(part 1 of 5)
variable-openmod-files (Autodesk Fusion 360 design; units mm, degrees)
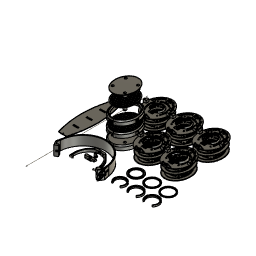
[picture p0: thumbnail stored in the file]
sketch "Pad Mount Start" plane through (0, 0, 0) normal (0, 0, 1) x axis (1, 0, 0)
  curve K1 (0, 53) -> (0, -53)
  curve K2 (-43, 0) -> (43, 0)
  curve K3 (0, 41) -> (0, -41)
  curve K4 (-31, 0) -> (31, 0)
  curve K5 (0, 43) -> (0, -43)
  curve K6 (-33, 0) -> (33, 0)
  line L1 (29.0688, 20.3542) -> (0, 0)
  line L2 (35.4865, 0) -> (0, 0)
  line L3 (20.8361, 33.3448) -> (0, 0)
  line L4 (39.3194, 0) -> (0, 0)
  curve K7 (0, -35.5) -> (0, 35.5)
  curve K8 (25.5, 0) -> (-25.5, 0)
  line L5 (29.0688, -20.3542) -> (0, 0)
  line L6 (20.8361, -33.3448) -> (0, 0)
  line L7 (0, 20) -> (0, 2.5)
  line L8 (-29.0688, -20.3542) -> (0, 0)
  line L9 (-20.8361, -33.3448) -> (0, 0)
  line L10 (-29.0688, 20.3542) -> (0, 0)
  line L11 (-20.8361, 33.3448) -> (0, 0)
  line L12 (37.023, 0) -> (0, 0)
  line L13 (11.725, -5.6147) -> (15.1969, -7.6193)
  line L14 (15.1969, 7.6193) -> (11.725, 5.6147)
  line L15 (1, 10.9545) -> (1, 6.9282)
  line L16 (6.5, -2.5981) -> (9.9868, -4.6112)
  line L17 (10.725, 7.3468) -> (14.1969, 9.3513)
  line L18 (1, 16.9706) -> (1, 12.9615)
  line L19 (11.43, 15.1775) -> (14.6475, 19.0119)
  line L20 (1, 23.9792) -> (1, 18.9737)
  line L21 (-1, 18.9737) -> (-1, 23.9792)
  line L22 (-14.6475, 19.0119) -> (-11.43, 15.1775)
  line L23 (-12.9621, 13.8919) -> (-16.1795, 17.7263)
  line L24 (-23.4412, 5.1487) -> (-18.5118, 4.2796)
  line L25 (-18.8591, 2.3099) -> (-23.7885, 3.1791)
  line L26 (-21.2666, -11.1236) -> (-16.9317, -8.6208)
  line L27 (-15.9317, -10.3529) -> (-20.2666, -12.8556)
  line L28 (-9.141, -22.191) -> (-7.4291, -17.4874)
  line L29 (-5.5497, -18.1714) -> (-7.2617, -22.8751)
  line L30 (7.2617, -22.8751) -> (5.5497, -18.1714)
  line L31 (7.4291, -17.4874) -> (9.141, -22.191)
  line L32 (20.2666, -12.8556) -> (15.9317, -10.3529)
  line L33 (16.9317, -8.6208) -> (21.2666, -11.1236)
  line L34 (23.7885, 3.1791) -> (18.8591, 2.3099)
  line L35 (18.5118, 4.2796) -> (23.4412, 5.1487)
  line L36 (16.1795, 17.7263) -> (12.9621, 13.8919)
  line L37 (-14.1969, 9.3513) -> (-10.725, 7.3468)
  line L38 (-1, 12.9615) -> (-1, 16.9706)
  line L39 (-11.725, 5.6147) -> (-15.1969, 7.6193)
  line L40 (-15.1969, -7.6193) -> (-11.725, -5.6147)
  line L41 (-9.9868, -4.6112) -> (-6.5, -2.5981)
  line L42 (-1, 6.9282) -> (-1, 10.9545)
  line L43 (8.9868, -6.3433) -> (5.5, -4.3301)
  line L44 (-5.5, -4.3301) -> (-8.9868, -6.3433)
  line L45 (-10.725, -7.3468) -> (-14.1969, -9.3513)
  line L46 (-1, -16.9706) -> (-1, -12.9615)
  line L47 (14.1969, -9.3513) -> (10.725, -7.3468)
  line L48 (1, -12.9615) -> (1, -16.9706)
  closed curve K9 centre (0, 0)
  closed curve K10 centre (0, 0)
  closed curve K11 centre (0, 0)
  circle C1 centre (0, 0) radius 24
  circle C2 centre (0, 0) radius 25.5
  circle C3 centre (0, 0) radius 29.5
  closed curve K12 centre (0, 0)
  arc A1 centre (0, 0) radius 17 clockwise from (15.1969, 7.6193) to (15.1969, -7.6193)
  arc A2 centre (0, 0) radius 13 clockwise from (11.725, 5.6147) to (11.725, -5.6147)
  arc A3 centre (0, 0) radius 7 clockwise from (1, 6.9282) to (6.5, -2.5981)
  arc A4 centre (0, 0) radius 11 clockwise from (1, 10.9545) to (9.9868, -4.6112)
  arc A5 centre (0, 0) radius 17 clockwise from (1, 16.9706) to (14.1969, 9.3513)
  arc A6 centre (0, 0) radius 13 clockwise from (1, 12.9615) to (10.725, 7.3468)
  arc A7 centre (0, 0) radius 24 clockwise from (14.6475, 19.0119) to (16.1795, 17.7263)
  arc A8 centre (0, 0) radius 19 clockwise from (1, 18.9737) to (11.43, 15.1775)
  arc A9 centre (0, 0) radius 24 clockwise from (-1, 23.9792) to (1, 23.9792)
  arc A10 centre (0, 0) radius 19 clockwise from (-11.43, 15.1775) to (-1, 18.9737)
  arc A11 centre (0, 0) radius 24 clockwise from (-16.1795, 17.7263) to (-14.6475, 19.0119)
  arc A12 centre (0, 0) radius 19 clockwise from (-18.5118, 4.2796) to (-12.9621, 13.8919)
  arc A13 centre (0, 0) radius 24 clockwise from (-23.7885, 3.1791) to (-23.4412, 5.1487)
  arc A14 centre (0, 0) radius 19 clockwise from (-16.9317, -8.6208) to (-18.8591, 2.3099)
  arc A15 centre (0, 0) radius 24 clockwise from (-20.2666, -12.8556) to (-21.2666, -11.1236)
  arc A16 centre (0, 0) radius 19 clockwise from (-7.4291, -17.4874) to (-15.9317, -10.3529)
  arc A17 centre (0, 0) radius 24 clockwise from (-7.2617, -22.8751) to (-9.141, -22.191)
  arc A18 centre (0, 0) radius 19 clockwise from (5.5497, -18.1714) to (-5.5497, -18.1714)
  arc A19 centre (0, 0) radius 24 clockwise from (9.141, -22.191) to (7.2617, -22.8751)
  arc A20 centre (0, 0) radius 19 clockwise from (15.9317, -10.3529) to (7.4291, -17.4874)
  arc A21 centre (0, 0) radius 24 clockwise from (21.2666, -11.1236) to (20.2666, -12.8556)
  arc A22 centre (0, 0) radius 19 clockwise from (18.8591, 2.3099) to (16.9317, -8.6208)
  arc A23 centre (0, 0) radius 24 clockwise from (23.4412, 5.1487) to (23.7885, 3.1791)
  arc A24 centre (0, 0) radius 19 clockwise from (12.9621, 13.8919) to (18.5118, 4.2796)
  arc A25 centre (0, 0) radius 13 clockwise from (-10.725, 7.3468) to (-1, 12.9615)
  arc A26 centre (0, 0) radius 17 clockwise from (-14.1969, 9.3513) to (-1, 16.9706)
  arc A27 centre (0, 0) radius 17 clockwise from (-15.1969, -7.6193) to (-15.1969, 7.6193)
  arc A28 centre (0, 0) radius 13 clockwise from (-11.725, -5.6147) to (-11.725, 5.6147)
  arc A29 centre (0, 0) radius 7 clockwise from (-6.5, -2.5981) to (-1, 6.9282)
  arc A30 centre (0, 0) radius 11 clockwise from (-9.9868, -4.6112) to (-1, 10.9545)
  arc A31 centre (0, 0) radius 7 clockwise from (5.5, -4.3301) to (-5.5, -4.3301)
  arc A32 centre (0, 0) radius 11 clockwise from (8.9868, -6.3433) to (-8.9868, -6.3433)
  arc A33 centre (0, 0) radius 17 clockwise from (-1, -16.9706) to (-14.1969, -9.3513)
  arc A34 centre (0, 0) radius 13 clockwise from (-1, -12.9615) to (-10.725, -7.3468)
  arc A35 centre (0, 0) radius 13 clockwise from (10.725, -7.3468) to (1, -12.9615)
  arc A36 centre (0, 0) radius 17 clockwise from (14.1969, -9.3513) to (1, -16.9706)
  circle C4 centre (0, 0) radius 5
  point P3 (0, -53)
  point P4 (0, 53)
  point P5 (43, 0)
  point P6 (-43, 0)
  point P1 (0, 0)
  point P2 (0, 0)
  point P8 (0, -41)
  point P9 (0, 41)
  point P10 (31, 0)
  point P11 (-31, 0)
  point P7 (0, 0)
  point P13 (0, -43)
  point P14 (0, 43)
  point P15 (33, 0)
  point P16 (-33, 0)
  point P17 (0, 0)
  point P20 (0, 0)
  point P21 (29.0688, 20.3542)
  point P23 (0, 0)
  point P24 (20.8361, 33.3448)
  point P27 (0, 35.5)
  point P28 (0, -35.5)
  point P29 (-25.5, 0)
  point P30 (25.5, 0)
  point P31 (0, 0)
  point P32 (29.0688, -20.3542)
  point P33 (0, 0)
  point P34 (20.8361, -33.3448)
  point P41 (0, 0)
  point P42 (-29.0688, 20.3542)
  point P43 (0, 0)
  point P44 (-20.8361, 33.3448)
  point P37 (0, 0)
  point P38 (-29.0688, -20.3542)
  point P39 (0, 0)
  point P40 (-20.8361, -33.3448)
  coincident K9 P3
  coincident K9 P4
  coincident K9 P5
  coincident K9 P6
  coincident P1 P2
  vertical K1
  coincident K10 P8
  coincident K10 P9
  coincident K10 P10
  coincident K10 P11
  coincident P1 P7
  perpendicular K2 K3
  coincident K11 P13
  coincident K11 P14
  coincident K11 P15
  coincident K11 P16
  concentric K9 K11
  perpendicular K4 K5
  concentric K11 C1
  concentric K9 C2
  concentric K9 C3
  horizontal L2
  coincident P17 P20
  coincident K11 P21
  horizontal L4
  coincident P7 P23
  coincident K11 P24
  coincident K12 P27
  coincident K12 P28
  coincident K12 P29
  coincident K12 P30
  concentric K10 K12
  parallel K3 K7
  symmetric P20 L2 P31
  symmetric P21 L2 P32
  symmetric L2 P23 P33
  symmetric L2 P24 P34
  symmetric P20 L7 P41
  symmetric P21 L7 P42
  symmetric P23 L7 P43
  symmetric P24 L7 P44
  symmetric P31 L7 P37
  symmetric P32 L7 P38
  symmetric P33 L7 P39
  symmetric P34 L7 P40
  horizontal L12
  dimension "d1" distance K9 = 106
  dimension "d2" = 86
  dimension "d3" distance K10 = 82
  dimension "d4" = 62
  dimension "d5" distance K11 = 86
  dimension "d6" = 66
  dimension "d7" diameter C1 = 48
  dimension "d8" diameter C2 = 51
  dimension "d9" diameter C3 = 59
  dimension "d10" angle L1 L2 = 35
  dimension "d11" angle L3 L4 = 58
  dimension "d12" distance K12 = 71
  dimension "d13" = 51
  dimension "d660" angle P16 = 20
extrude "Extrude1" new body sketch "Pad Mount Start" profile of K9 K11 along normal blind 2
extrude "Extrude2" add sketch "Pad Mount Start" profile of K10 K11 C2 C3 along normal blind 5
extrude "Extrude3" add sketch "Pad Mount Start" profile of C1 C2 A7 A9 A11 A13 A15 A17 A19 A21 A23 along normal blind 2.5
extrude "Extrude4" add sketch "Pad Mount Start" profile of C1 A1 L13 L14 A2 L15 A3 L16 A4 A5 L17 L18 A6 A7 L19 A8 L20 A9 L21 A10 L22 A11 L23 A12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 along normal blind 1.5
component_from_bodies "Body->Comp1"
sketch "Sketch2" plane through (0, 0, 5) normal (0, 0, 1) x axis (-1, 0, 0)
  line L1 (-20.8361, -33.3448) -> (0, 0)
  line L2 (-29.0688, -20.3542) -> (0, 0)
  line L3 (-29.0688, 20.3542) -> (0, 0)
  line L4 (-20.8361, 33.3448) -> (0, 0)
  line L5 (20.8361, 33.3448) -> (0, 0)
  line L6 (29.0688, 20.3542) -> (0, 0)
  line L7 (29.0688, -20.3542) -> (0, 0)
  line L8 (20.8361, -33.3448) -> (0, 0)
  curve K1 (0, 41) -> (0, -41)
  curve K2 (-31, 0) -> (31, 0)
  curve K3 (-27, 0) -> (27, 0)
  curve K4 (0, -37) -> (0, 37)
  circle C1 centre (0, 0) radius 25.5
  closed curve K5 centre (0, 0)
  closed curve K6 centre (0, 0)
  closed curve K7 centre (0, 0)
  circle C2 centre (0, 0) radius 29.5
  circle C3 centre (0, 0) radius 33.5
  point P20 (0, -41)
  point P21 (0, 41)
  point P22 (31, 0)
  point P23 (-31, 0)
  point P15 (0, 0)
  point P16 (0, 0)
  point P25 (27, 0)
  point P26 (-27, 0)
  point P27 (0, 37)
  point P28 (0, -37)
  point P4 (0, 0)
  point P24 (0, 0)
  point P9 (0, 0)
  point P29 (0, 0)
  coincident K6 P20
  coincident K6 P21
  coincident K6 P22
  coincident K6 P23
  coincident P15 P16
  coincident K7 P25
  coincident K7 P26
  coincident K7 P27
  coincident K7 P28
  coincident P4 P24
  parallel K2 K3
  coincident P9 P29
  concentric K6 C3
  dimension "d37" distance K6 = 82
  dimension "d38" = 62
  dimension "d41" distance K7 = 54
  dimension "d42" = 74
  dimension "d43" diameter C2 = 59
  dimension "d44" diameter C3 = 67
extrude "Extrude2" cut sketch "Sketch2" profile of L1 L2 L3 L4 L5 L6 L7 L8 K6 K7 C2 C3 against normal blind 5
sketch "Sketch3" plane through (0, 0, 0) normal (0, 0, -1) x axis (1, 0, 0)
  line L1 (17.7523, -28.4096) -> (15.6326, -25.0174)
  line L2 (-15.6326, -25.0174) -> (-17.7523, -28.4096)
  line L3 (-27.3973, -19.1838) -> (-24.0432, -16.8352)
  line L4 (-24.0432, 16.8352) -> (-27.3973, 19.1838)
  line L5 (-17.7523, 28.4096) -> (-15.6326, 25.0174)
  line L6 (15.6326, 25.0174) -> (17.7523, 28.4096)
  line L7 (27.3973, 19.1838) -> (24.0432, 16.8352)
  line L8 (24.0432, -16.8352) -> (27.3973, -19.1838)
  line L9 (12.9621, -13.8919) -> (16.1795, -17.7263)
  line L10 (23.4412, -5.1487) -> (18.5118, -4.2796)
  line L11 (18.8591, -2.3099) -> (23.7885, -3.1791)
  line L12 (21.2666, 11.1236) -> (16.9317, 8.6208)
  line L13 (15.9317, 10.3529) -> (20.2666, 12.8556)
  line L14 (9.141, 22.191) -> (7.4291, 17.4874)
  line L15 (5.5497, 18.1714) -> (7.2617, 22.8751)
  line L16 (-7.2617, 22.8751) -> (-5.5497, 18.1714)
  line L17 (-7.4291, 17.4874) -> (-9.141, 22.191)
  line L18 (-20.2666, 12.8556) -> (-15.9317, 10.3529)
  line L19 (-16.9317, 8.6208) -> (-21.2666, 11.1236)
  line L20 (-23.7885, -3.1791) -> (-18.8591, -2.3099)
  line L21 (-18.5118, -4.2796) -> (-23.4412, -5.1487)
  line L22 (-16.1795, -17.7263) -> (-12.9621, -13.8919)
  line L23 (-11.43, -15.1775) -> (-14.6475, -19.0119)
  line L24 (-1, -23.9792) -> (-1, -18.9737)
  line L25 (-1, -10.9545) -> (-1, -6.9282)
  line L26 (-6.5, 2.5981) -> (-9.9868, 4.6112)
  line L27 (-1, 12.9615) -> (-1, 16.9706)
  line L28 (-14.1969, 9.3513) -> (-10.725, 7.3468)
  line L29 (1, -12.9615) -> (1, -16.9706)
  line L30 (14.1969, -9.3513) -> (10.725, -7.3468)
  line L31 (11.725, -5.6147) -> (15.1969, -7.6193)
  line L32 (15.1969, 7.6193) -> (11.725, 5.6147)
  line L33 (-11.725, 5.6147) -> (-15.1969, 7.6193)
  line L34 (-15.1969, -7.6193) -> (-11.725, -5.6147)
  line L35 (-1, -16.9706) -> (-1, -12.9615)
  line L36 (-10.725, -7.3468) -> (-14.1969, -9.3513)
  line L37 (-8.9868, 6.3433) -> (-5.5, 4.3301)
  line L38 (5.5, 4.3301) -> (8.9868, 6.3433)
  line L39 (1, 16.9706) -> (1, 12.9615)
  line L40 (10.725, 7.3468) -> (14.1969, 9.3513)
  line L41 (9.9868, 4.6112) -> (6.5, 2.5981)
  line L42 (1, -6.9282) -> (1, -10.9545)
  line L43 (1, -18.9737) -> (1, -23.9792)
  line L44 (14.6475, -19.0119) -> (11.43, -15.1775)
  line L45 (22.8469, -24.5003) -> (0, 0)
  line L46 (33.5, 0) -> (0, 0)
  line L47 (-22.8469, -24.5003) -> (0, 0)
  line L48 (-33.5, 0) -> (0, 0)
  line L49 (-22.8469, 24.5003) -> (0, 0)
  line L50 (22.8469, 24.5003) -> (0, 0)
  arc A1 centre (0, 0) radius 33.5 clockwise from (17.7523, -28.4096) to (-17.7523, -28.4096)
  arc A2 centre (0, 0) radius 29.5 clockwise from (15.6326, -25.0174) to (-15.6326, -25.0174)
  closed curve K1 centre (0, 0)
  closed curve K2 centre (0, 0)
  arc A3 centre (0, 0) radius 33.5 clockwise from (-17.7523, 28.4096) to (17.7523, 28.4096)
  arc A4 centre (0, 0) radius 29.5 clockwise from (-15.6326, 25.0174) to (15.6326, 25.0174)
  closed curve K3 centre (0, 0)
  closed curve K4 centre (0, 0)
  arc A5 centre (0, 0) radius 24 clockwise from (23.4412, -5.1487) to (16.1795, -17.7263)
  arc A6 centre (0, 0) radius 19 clockwise from (18.5118, -4.2796) to (12.9621, -13.8919)
  arc A7 centre (0, 0) radius 19 clockwise from (16.9317, 8.6208) to (18.8591, -2.3099)
  arc A8 centre (0, 0) radius 24 clockwise from (21.2666, 11.1236) to (23.7885, -3.1791)
  arc A9 centre (0, 0) radius 19 clockwise from (7.4291, 17.4874) to (15.9317, 10.3529)
  arc A10 centre (0, 0) radius 24 clockwise from (9.141, 22.191) to (20.2666, 12.8556)
  arc A11 centre (0, 0) radius 19 clockwise from (-5.5497, 18.1714) to (5.5497, 18.1714)
  arc A12 centre (0, 0) radius 24 clockwise from (-7.2617, 22.8751) to (7.2617, 22.8751)
  arc A13 centre (0, 0) radius 19 clockwise from (-15.9317, 10.3529) to (-7.4291, 17.4874)
  arc A14 centre (0, 0) radius 24 clockwise from (-20.2666, 12.8556) to (-9.141, 22.191)
  arc A15 centre (0, 0) radius 19 clockwise from (-18.8591, -2.3099) to (-16.9317, 8.6208)
  arc A16 centre (0, 0) radius 24 clockwise from (-23.7885, -3.1791) to (-21.2666, 11.1236)
  arc A17 centre (0, 0) radius 19 clockwise from (-12.9621, -13.8919) to (-18.5118, -4.2796)
  arc A18 centre (0, 0) radius 24 clockwise from (-16.1795, -17.7263) to (-23.4412, -5.1487)
  arc A19 centre (0, 0) radius 19 clockwise from (-1, -18.9737) to (-11.43, -15.1775)
  arc A20 centre (0, 0) radius 24 clockwise from (-1, -23.9792) to (-14.6475, -19.0119)
  arc A21 centre (0, 0) radius 11 clockwise from (-1, -10.9545) to (-9.9868, 4.6112)
  arc A22 centre (0, 0) radius 7 clockwise from (-1, -6.9282) to (-6.5, 2.5981)
  arc A23 centre (0, 0) radius 17 clockwise from (-14.1969, 9.3513) to (-1, 16.9706)
  arc A24 centre (0, 0) radius 13 clockwise from (-10.725, 7.3468) to (-1, 12.9615)
  arc A25 centre (0, 0) radius 17 clockwise from (14.1969, -9.3513) to (1, -16.9706)
  arc A26 centre (0, 0) radius 13 clockwise from (10.725, -7.3468) to (1, -12.9615)
  arc A27 centre (0, 0) radius 17 clockwise from (15.1969, 7.6193) to (15.1969, -7.6193)
  arc A28 centre (0, 0) radius 13 clockwise from (11.725, 5.6147) to (11.725, -5.6147)
  arc A29 centre (0, 0) radius 17 clockwise from (-15.1969, -7.6193) to (-15.1969, 7.6193)
  arc A30 centre (0, 0) radius 13 clockwise from (-11.725, -5.6147) to (-11.725, 5.6147)
  arc A31 centre (0, 0) radius 17 clockwise from (-1, -16.9706) to (-14.1969, -9.3513)
  arc A32 centre (0, 0) radius 13 clockwise from (-1, -12.9615) to (-10.725, -7.3468)
  arc A33 centre (0, 0) radius 11 clockwise from (-8.9868, 6.3433) to (8.9868, 6.3433)
  arc A34 centre (0, 0) radius 7 clockwise from (-5.5, 4.3301) to (5.5, 4.3301)
  circle C1 centre (0, 0) radius 5
  arc A35 centre (0, 0) radius 17 clockwise from (1, 16.9706) to (14.1969, 9.3513)
  arc A36 centre (0, 0) radius 13 clockwise from (1, 12.9615) to (10.725, 7.3468)
  arc A37 centre (0, 0) radius 11 clockwise from (9.9868, 4.6112) to (1, -10.9545)
  arc A38 centre (0, 0) radius 7 clockwise from (6.5, 2.5981) to (1, -6.9282)
  arc A39 centre (0, 0) radius 19 clockwise from (11.43, -15.1775) to (1, -18.9737)
  arc A40 centre (0, 0) radius 24 clockwise from (14.6475, -19.0119) to (1, -23.9792)
  closed curve K5 centre (0, 0)
  circle C2 centre (0, 0) radius 33.5
  circle C3 centre (-22.8469, -24.5003) radius 2.2
  circle C4 centre (-22.8469, -24.5003) radius 4
  circle C5 centre (-22.8469, -24.5003) radius 4.5
  circle C6 centre (22.8469, -24.5003) radius 2.2
  circle C7 centre (22.8469, -24.5003) radius 4
  circle C8 centre (22.8469, -24.5003) radius 4.5
  circle C9 centre (-22.8469, 24.5003) radius 4.5
  circle C10 centre (-22.8469, 24.5003) radius 4
  circle C11 centre (-22.8469, 24.5003) radius 2.2
  circle C12 centre (22.8469, 24.5003) radius 4.5
  circle C13 centre (22.8469, 24.5003) radius 4
  circle C14 centre (22.8469, 24.5003) radius 2.2
  point P1 (0, 0)
  point P92 (0, 0)
  point P93 (22.8469, -24.5003)
  point P5 (0, 0)
  point P95 (0, 0)
  point P96 (-22.8469, -24.5003)
  point P100 (0, 0)
  point P101 (22.8469, 24.5003)
  point P98 (0, 0)
  point P99 (-22.8469, 24.5003)
  point P102 (-22.8469, -24.5003)
  point P103 (-22.8469, -24.5003)
  point P104 (-22.8469, -24.5003)
  point P105 (22.8469, -24.5003)
  concentric A1 C2
  horizontal L46
  coincident P1 P92
  coincident C2 P93
  horizontal L48
  coincident P5 P95
  coincident C2 P96
  symmetric P92 L46 P100
  symmetric P93 L46 P101
  symmetric L46 P95 P98
  symmetric L46 P96 P99
  coincident P96 P102
  coincident P96 P103
  coincident P96 P104
  coincident P93 P105
  concentric C6 C7
  concentric C6 C8
  symmetric L48 C3 C11
  symmetric L48 C4 C10
  symmetric L48 C5 C9
  symmetric L48 C6 C14
  symmetric L48 C7 C13
  symmetric L48 C8 C12
  dimension "d59" diameter C2 = 67
  dimension "d60" angle L45 L46 = 47
  dimension "d61" angle L47 L48 = 47
  dimension "d62" diameter C3 = 4.4
  dimension "d63" diameter C4 = 8
  dimension "d64" diameter C5 = 9
  dimension "d65" diameter C6 = 4.4
  dimension "d66" diameter C7 = 8
  dimension "d67" diameter C8 = 9
extrude "Extrude5" cut sketch "Sketch3" profile of C3 C6 C11 C14 against normal blind 5
extrude "Extrude6" cut sketch "Sketch3" profile of C3 C4 C6 C7 C10 C11 C13 C14 against normal blind 3
sketch "Sketch4" plane through (0, 0, 5) normal (0, 0, 1) x axis (-1, 0, 0)
  line L1 (-15.6326, -25.0174) -> (-17.7523, -28.4096)
  line L2 (17.7523, -28.4096) -> (15.6326, -25.0174)
  line L3 (24.0432, -16.8352) -> (27.3973, -19.1838)
  line L4 (27.3973, 19.1838) -> (24.0432, 16.8352)
  line L5 (15.6326, 25.0174) -> (17.7523, 28.4096)
  line L6 (-17.7523, 28.4096) -> (-15.6326, 25.0174)
  line L7 (-24.0432, 16.8352) -> (-27.3973, 19.1838)
  line L8 (-27.3973, -19.1838) -> (-24.0432, -16.8352)
  circle C1 centre (22.8469, -24.5003) radius 2.2
  circle C2 centre (22.8469, 24.5003) radius 2.2
  circle C3 centre (-22.8469, -24.5003) radius 2.2
  circle C4 centre (-22.8469, 24.5003) radius 2.2
  arc A1 centre (0, 0) radius 29.5 clockwise from (15.6326, -25.0174) to (-15.6326, -25.0174)
  arc A2 centre (0, 0) radius 33.5 clockwise from (17.7523, -28.4096) to (-17.7523, -28.4096)
  closed curve K1 centre (0, 0)
  closed curve K2 centre (0, 0)
  arc A3 centre (0, 0) radius 29.5 clockwise from (-15.6326, 25.0174) to (15.6326, 25.0174)
  arc A4 centre (0, 0) radius 33.5 clockwise from (-17.7523, 28.4096) to (17.7523, 28.4096)
  closed curve K3 centre (0, 0)
  closed curve K4 centre (0, 0)
  circle C5 centre (0, 0) radius 25.5
  closed curve K5 centre (0, 0)
  circle C6 centre (22.8469, -24.5003) radius 4.5
  circle C7 centre (-22.8469, -24.5003) radius 4.5
  circle C8 centre (22.8469, 24.5003) radius 4.5
  circle C9 centre (-22.8469, 24.5003) radius 4.5
  concentric C1 C6
  concentric C3 C7
  concentric C2 C8
  concentric C4 C9
  dimension "d72" diameter C6 = 9
  dimension "d73" diameter C7 = 9
  dimension "d74" diameter C8 = 9
  dimension "d75" diameter C9 = 9
extrude "Extrude7" add sketch "Sketch4" profile of K5 C6 C7 C8 C9 against normal blind 3
extrude "Extrude8" cut of existing geometry blind -1
work_plane "WorkPlane1" AlongDistance 20
sketch "Driver Clamp" plane through (0, 0, 20) normal (0, 0, 1) x axis (1, 0, 0)
  curve K1 (0, 55) -> (0, -55)
  curve K2 (-45, 0) -> (45, 0)
  line L1 (29.0688, -20.3542) -> (0, 0)
  line L2 (20.8361, -33.3448) -> (0, 0)
  line L3 (-20.8361, -33.3448) -> (0, 0)
  line L4 (-29.0688, -20.3542) -> (0, 0)
  line L5 (-29.0688, 20.3542) -> (0, 0)
  line L6 (-20.8361, 33.3448) -> (0, 0)
  curve K3 (0, 41) -> (0, -41)
  curve K4 (-31, 0) -> (31, 0)
  curve K5 (-27, 0) -> (27, 0)
  curve K6 (0, -37) -> (0, 37)
  line L7 (20.8361, 33.3448) -> (0, 0)
  line L8 (29.0688, 20.3542) -> (0, 0)
  closed curve K7 centre (0, 0)
  circle C1 centre (22.8469, -24.5003) radius 2.2
  circle C2 centre (-22.8469, -24.5003) radius 2.2
  circle C3 centre (-22.8469, 24.5003) radius 2.2
  circle C4 centre (22.8469, 24.5003) radius 2.2
  circle C5 centre (0, 0) radius 25.2
  circle C6 centre (0, 0) radius 27.5
  circle C7 centre (0, 0) radius 29.5
  circle C8 centre (0, 0) radius 33.5
  closed curve K8 centre (0, 0)
  closed curve K9 centre (0, 0)
  point P3 (0, -55)
  point P4 (0, 55)
  point P5 (45, 0)
  point P6 (-45, 0)
  point P1 (0, 0)
  point P2 (0, 0)
  point P11 (0, 0)
  point P12 (0, 0)
  point P29 (0, -41)
  point P30 (0, 41)
  point P31 (31, 0)
  point P32 (-31, 0)
  point P33 (27, 0)
  point P34 (-27, 0)
  point P35 (0, 37)
  point P36 (0, -37)
  point P13 (0, 0)
  point P15 (0, 0)
  point P25 (0, 0)
  point P28 (0, 0)
  coincident K7 P3
  coincident K7 P4
  coincident K7 P5
  coincident K7 P6
  coincident P1 P2
  vertical K1
  coincident P1 P11
  coincident P1 P12
  coincident K8 P29
  coincident K8 P30
  coincident K8 P31
  coincident K8 P32
  coincident K9 P33
  coincident K9 P34
  coincident K9 P35
  coincident K9 P36
  coincident P13 P15
  parallel K4 K5
  coincident P25 P28
  concentric C8 K8
  dimension "d81" distance K7 = 110
  dimension "d82" = 90
  dimension "d83" diameter C5 = 50.4
  dimension "d84" diameter C6 = 55
  dimension "d85" distance K8 = 82
  dimension "d86" = 62
  dimension "d87" distance K9 = 54
  dimension "d88" = 74
  dimension "d89" diameter C7 = 59
  dimension "d90" diameter C8 = 67
extrude "Extrude9" new body sketch "Driver Clamp" profile of K7 C1 C2 C3 C4 C5 C6 L1 L2 L3 L4 L5 L6 C7 C8 K8 K9 L7 L8 along normal blind 2
sketch "Sketch6" plane through (0, 0, 22) normal (0, 0, 1) x axis (-1, 0, 0)
  line L1 (-24.0432, 16.8352) -> (-27.3973, 19.1838)
  line L2 (-27.3973, -19.1838) -> (-24.0432, -16.8352)
  line L3 (-17.7523, 28.4096) -> (-15.6326, 25.0174)
  line L4 (15.6326, 25.0174) -> (17.7523, 28.4096)
  line L5 (-15.6326, -25.0174) -> (-17.7523, -28.4096)
  line L6 (17.7523, -28.4096) -> (15.6326, -25.0174)
  line L7 (27.3973, 19.1838) -> (24.0432, 16.8352)
  line L8 (24.0432, -16.8352) -> (27.3973, -19.1838)
  line L9 (8, 35.5) -> (-8, 35.5)
  line L10 (8, 23.5) -> (8, 35.5)
  line L11 (-8, 23.5) -> (8, 23.5)
  line L12 (-8, 35.5) -> (-8, 23.5)
  line L13 (8, 23.5) -> (-8, 35.5)
  line L14 (-8, 23.5) -> (8, 35.5)
  closed curve K1 centre (0, 0)
  arc A1 centre (0, 0) radius 27.5 clockwise from (-26.4189, -7.6348) to (-26.4189, 7.6348)
  closed curve K2 centre (0, 0)
  closed curve K3 centre (0, 0)
  arc A2 centre (0, 0) radius 29.5 clockwise from (-15.6326, 25.0174) to (15.6326, 25.0174)
  arc A3 centre (0, 0) radius 33.5 clockwise from (-17.7523, 28.4096) to (17.7523, 28.4096)
  circle C1 centre (-22.8469, -24.5003) radius 2.2
  circle C2 centre (-22.8469, 24.5003) radius 2.2
  circle C3 centre (22.8469, -24.5003) radius 2.2
  circle C4 centre (0, 0) radius 25.2
  circle C5 centre (22.8469, 24.5003) radius 2.2
  arc A4 centre (0, 0) radius 29.5 clockwise from (15.6326, -25.0174) to (-15.6326, -25.0174)
  arc A5 centre (0, 0) radius 33.5 clockwise from (17.7523, -28.4096) to (-17.7523, -28.4096)
  closed curve K4 centre (0, 0)
  closed curve K5 centre (0, 0)
  closed curve K6 centre (0, 0)
  arc A6 centre (0, 0) radius 27.5 clockwise from (26.4189, 7.6348) to (26.4189, -7.6348)
  closed curve K7 centre (0, 0)
  point P31 (0, 29.5)
  point P29 (8, 23.5)
  point P30 (-8, 23.5)
  point P28 (8, 35.5)
  horizontal L9
  perpendicular L9 L10
  parallel L9 L11
  parallel L10 L12
  coincident L13 P31
  coincident L14 P31
  midpoint A2 P31
  dimension "d93" distance P29 P30 = 16
  dimension "d94" distance P28 P29 = 12
extrude "Extrude10" cut sketch "Sketch6" profile of A2 C4 L10 L12 against normal blind 2
extrude "Extrude11" add sketch "Sketch6" profile of A2 L3 A3 L4 L10 L12 against normal blind 2
sketch "Sketch7" plane through (0, 0, 22) normal (0, 0, 1) x axis (-1, 0, 0)
  line L1 (27.3973, 19.1838) -> (24.0432, 16.8352)
  line L2 (24.0432, -16.8352) -> (27.3973, -19.1838)
  line L3 (-15.6326, -25.0174) -> (-17.7523, -28.4096)
  line L4 (17.7523, -28.4096) -> (15.6326, -25.0174)
  line L5 (-8, 32.5308) -> (-8, 23.8964)
  line L6 (8, 23.8964) -> (8, 32.5308)
  line L7 (-24.0432, 16.8352) -> (-27.3973, 19.1838)
  line L8 (-27.3973, -19.1838) -> (-24.0432, -16.8352)
  line L9 (25.2, 0) -> (0, 0)
  line L10 (-25.2, 0) -> (0, 0)
  line L11 (19.4454, 19.4454) -> (0, 0)
  line L12 (27.5, 0) -> (0, 0)
  line L13 (-19.4454, 19.4454) -> (0, 0)
  line L14 (-27.5, 0) -> (0, 0)
  closed curve K1 centre (0, 0)
  closed curve K2 centre (0, 0)
  closed curve K3 centre (0, 0)
  closed curve K4 centre (0, 0)
  arc A1 centre (0, 0) radius 27.5 clockwise from (26.4189, 7.6348) to (26.4189, -7.6348)
  arc A2 centre (0, 0) radius 29.5 clockwise from (15.6326, -25.0174) to (-15.6326, -25.0174)
  arc A3 centre (0, 0) radius 33.5 clockwise from (17.7523, -28.4096) to (-17.7523, -28.4096)
  circle C1 centre (22.8469, 24.5003) radius 2.2
  circle C2 centre (22.8469, -24.5003) radius 2.2
  circle C3 centre (-22.8469, 24.5003) radius 2.2
  circle C4 centre (-22.8469, -24.5003) radius 2.2
  arc A4 centre (0, 0) radius 33.5 clockwise from (-8, 32.5308) to (8, 32.5308)
  arc A5 centre (0, 0) radius 25.2 clockwise from (8, 23.8964) to (-8, 23.8964)
  closed curve K5 centre (0, 0)
  arc A6 centre (0, 0) radius 27.5 clockwise from (-26.4189, -7.6348) to (-26.4189, 7.6348)
  closed curve K6 centre (0, 0)
  closed curve K7 centre (0, 0)
  circle C5 centre (0, 0) radius 21
  circle C6 centre (0, 0) radius 25.2
  circle C7 centre (0, 0) radius 27.5
  point P1 (0, 0)
  point P27 (0, 0)
  point P20 (8, 23.8964)
  point P2 (0, 0)
  point P29 (0, 0)
  point P31 (0, 0)
  point P34 (0, 0)
  point P35 (19.4454, 19.4454)
  point P37 (-19.4454, 19.4454)
  coincident P1 P27
  concentric K1 C6
  coincident P20 C6
  horizontal L9
  coincident P2 P29
  horizontal L10
  coincident P2 P31
  concentric K1 C7
  horizontal L12
  coincident P2 P34
  coincident C7 P35
  horizontal L14
  coincident C7 P37
  dimension "d99" diameter C5 = 42
  dimension "d102" diameter C7 = 55
  dimension "d103" angle L11 L12 = 45
  dimension "d104" angle L13 L14 = 45
extrude "Extrude12" add sketch "Sketch7" profile of A1 A5 A6 C5 C6 C7 L11 L13 along normal blind 4
chamfer "Chamfer1" distance 4.2 Rotate Angle 40
chamfer "Chamfer2" distance 4 Rotate Angle 45
sketch "Sketch8" plane through (0, 0, 22) normal (0, 0, 1) x axis (-1, 0, 0)
  line L1 (-27.3973, -19.1838) -> (-24.0432, -16.8352)
  line L2 (-24.0432, 16.8352) -> (-27.3973, 19.1838)
  line L3 (-17.8191, 17.8191) -> (-19.4454, 19.4454)
  line L4 (-8, 32.5308) -> (-8, 23.8964)
  line L5 (8, 23.8964) -> (8, 32.5308)
  line L6 (19.4454, 19.4454) -> (17.8191, 17.8191)
  line L7 (27.3973, 19.1838) -> (24.0432, 16.8352)
  line L8 (24.0432, -16.8352) -> (27.3973, -19.1838)
  line L9 (-15.6326, -25.0174) -> (-17.7523, -28.4096)
  line L10 (17.7523, -28.4096) -> (15.6326, -25.0174)
  curve K1 (0, 52.8) -> (0, -52.8)
  curve K2 (-42.8, 0) -> (42.8, 0)
  curve K3 (0, 50.8) -> (0, -50.8)
  curve K4 (-40.8, 0) -> (40.8, 0)
  line L11 (-8, 32.5308) -> (8, 32.5308)
  line L12 (-8, 55.0308) -> (-8, 32.5308)
  line L13 (8, 55.0308) -> (-8, 55.0308)
  line L14 (8, 32.5308) -> (8, 55.0308)
  line L15 (-6, 53.0308) -> (-6, 32.5308)
  line L16 (6, 53.0308) -> (-6, 53.0308)
  line L17 (6, 32.5308) -> (6, 53.0308)
  line L18 (17.2573, 46.032) -> (8, 49.8139)
  line L19 (18.1032, 47.8443) -> (17.2573, 46.032)
  line L20 (-17.2573, 46.032) -> (-8, 49.8139)
  line L21 (-18.1032, 47.8443) -> (-17.2573, 46.032)
  line L22 (6, 55.0308) -> (6, 53.0308)
  line L23 (-6, 55.0308) -> (-6, 53.0308)
  line L24 (-8, 54.1239) -> (-6, 55.0308)
  line L25 (8, 54.1239) -> (6, 55.0308)
  arc A1 centre (0, 0) radius 27.5 clockwise from (26.4189, -7.6348) to (-26.4189, -7.6348)
  closed curve K5 centre (0, 0)
  closed curve K6 centre (0, 0)
  closed curve K7 centre (0, 0)
  arc A2 centre (0, 0) radius 27.5 clockwise from (-26.4189, 7.6348) to (-19.4454, 19.4454)
  arc A3 centre (0, 0) radius 25.2 clockwise from (-17.8191, 17.8191) to (-8, 23.8964)
  arc A4 centre (0, 0) radius 33.5 clockwise from (-8, 32.5308) to (8, 32.5308)
  arc A5 centre (0, 0) radius 25.2 clockwise from (8, 23.8964) to (17.8191, 17.8191)
  arc A6 centre (0, 0) radius 27.5 clockwise from (19.4454, 19.4454) to (26.4189, 7.6348)
  closed curve K8 centre (0, 0)
  closed curve K9 centre (0, 0)
  closed curve K10 centre (0, 0)
  closed curve K11 centre (0, 0)
  arc A7 centre (0, 0) radius 29.5 clockwise from (15.6326, -25.0174) to (-15.6326, -25.0174)
  arc A8 centre (0, 0) radius 33.5 clockwise from (17.7523, -28.4096) to (-17.7523, -28.4096)
  circle C1 centre (22.8469, 24.5003) radius 2.2
  circle C2 centre (22.8469, -24.5003) radius 2.2
  circle C3 centre (-22.8469, 24.5003) radius 2.2
  circle C4 centre (-22.8469, -24.5003) radius 2.2
  closed curve K12 centre (0, 0)
  closed curve K13 centre (0, 0)
  point P32 (0, -52.8)
  point P33 (0, 52.8)
  point P34 (42.8, 0)
  point P35 (-42.8, 0)
  point P1 (0, 0)
  point P31 (0, 0)
  point P37 (0, -50.8)
  point P38 (0, 50.8)
  point P39 (40.8, 0)
  point P40 (-40.8, 0)
  point P14 (8, 32.5308)
  point P41 (8, 32.5308)
  point P49 (8, 49.8139)
  point P50 (17.2573, 46.032)
  point P51 (18.1032, 47.8443)
  point P52 (-8, 49.8139)
  point P53 (-17.2573, 46.032)
  point P54 (-18.1032, 47.8443)
  point P55 (6, 55.0308)
  point P56 (-6, 55.0308)
  point P57 (-8, 54.1239)
  point P58 (8, 54.1239)
  point P42 (-8, 32.5308)
  point P44 (8, 55.0308)
  coincident K12 P32
  coincident K12 P33
  coincident K12 P34
  coincident K12 P35
  coincident P1 P31
  vertical K1
  coincident K13 P37
  coincident K13 P38
  coincident K13 P39
  coincident K13 P40
  concentric A1 K13
  perpendicular K2 K3
  horizontal L11
  vertical L12
  horizontal L13
  vertical L14
  coincident P14 P41
  coincident L14 P49
  coincident K13 P49
  coincident K13 P50
  coincident K12 P51
  coincident K13 P52
  coincident L12 P52
  coincident K13 P53
  coincident K12 P54
  coincident L13 P55
  perpendicular L13 L22
  coincident L13 P56
  perpendicular L13 L23
  coincident L12 P57
  coincident K11 P57
  coincident L14 P58
  coincident K11 P58
  dimension "d111" distance K12 = 105.6
  dimension "d112" = 85.6
  dimension "d113" distance K13 = 101.6
  dimension "d114" = 81.6
  dimension "d115" distance P41 P42 = 16
  dimension "d116" distance P41 P44 = 22.5
  dimension "d117" = 2
  dimension "d118" distance P49 P50 = 10
  dimension "d119" distance P50 P51 = 2
  dimension "d120" distance P52 P53 = 10
  dimension "d121" distance P53 P54 = 2
extrude "Extrude13" add sketch "Sketch8" profile of K11 L13 L24 L25 against normal blind 2
extrude "Extrude14" add sketch "Sketch8" profile of K11 K12 K13 L12 L13 L14 L15 L17 L16 L19 L21 L24 L25 along normal blind 10.2
sketch "3.5mm Socket" plane through (0, -53.0308, 0) normal (0, 1, 0) x axis (-1, 0, 0)
  line L1 (6, 22) -> (-6, 22)
  line L2 (6, 32.2) -> (6, 22)
  line L3 (-6, 32.2) -> (6, 32.2)
  line L4 (-6, 22) -> (-6, 32.2)
  circle C1 centre (0, 27.1) radius 3.15
  dimension "d126" diameter C1 = 6.3
extrude "Extrude15" cut sketch "3.5mm Socket" profile of C1 against normal blind 2
chamfer "Chamfer3" distance 10.2 Rotate Angle 45
sketch "Sketch23" plane through (0, 0, 22) normal (0, 0, 1) x axis (-1, 0, 0)
  line L1 (-8, 54.1239) -> (-8, 51.8694)
  line L2 (8, 51.8694) -> (8, 54.1239)
  line L3 (17.2573, 46.032) -> (18.1032, 47.8443)
  line L4 (6, 53.0308) -> (6, 50.2477)
  line L5 (-6, 53.0308) -> (6, 53.0308)
  line L6 (-6, 50.2477) -> (-6, 53.0308)
  line L7 (-18.1032, 47.8443) -> (-17.2573, 46.032)
  line L8 (-27.3973, -19.1838) -> (-24.0432, -16.8352)
  line L9 (-24.0432, 16.8352) -> (-27.3973, 19.1838)
  line L10 (-17.8191, 17.8191) -> (-19.4454, 19.4454)
  line L11 (-8, 32.5308) -> (-8, 23.8964)
  line L12 (8, 23.8964) -> (8, 32.5308)
  line L13 (19.4454, 19.4454) -> (17.8191, 17.8191)
  line L14 (27.3973, 19.1838) -> (24.0432, 16.8352)
  line L15 (24.0432, -16.8352) -> (27.3973, -19.1838)
  line L16 (-15.6326, -25.0174) -> (-17.7523, -28.4096)
  line L17 (17.7523, -28.4096) -> (15.6326, -25.0174)
  closed curve K1 centre (0, 0)
  closed curve K2 centre (0, 0)
  closed curve K3 centre (0, 0)
  closed curve K4 centre (0, 0)
  closed curve K5 centre (0, 0)
  arc A1 centre (0, 0) radius 27.5 clockwise from (26.4189, -7.6348) to (-26.4189, -7.6348)
  closed curve K6 centre (0, 0)
  closed curve K7 centre (0, 0)
  closed curve K8 centre (0, 0)
  arc A2 centre (0, 0) radius 27.5 clockwise from (-26.4189, 7.6348) to (-19.4454, 19.4454)
  arc A3 centre (0, 0) radius 25.2 clockwise from (-17.8191, 17.8191) to (-8, 23.8964)
  arc A4 centre (0, 0) radius 33.5 clockwise from (-8, 32.5308) to (8, 32.5308)
  arc A5 centre (0, 0) radius 25.2 clockwise from (8, 23.8964) to (17.8191, 17.8191)
  arc A6 centre (0, 0) radius 27.5 clockwise from (19.4454, 19.4454) to (26.4189, 7.6348)
  closed curve K9 centre (0, 0)
  closed curve K10 centre (0, 0)
  closed curve K11 centre (0, 0)
  arc A7 centre (0, 0) radius 29.5 clockwise from (15.6326, -25.0174) to (-15.6326, -25.0174)
  arc A8 centre (0, 0) radius 33.5 clockwise from (17.7523, -28.4096) to (-17.7523, -28.4096)
  circle C1 centre (22.8469, 24.5003) radius 2.2
  circle C2 centre (22.8469, -24.5003) radius 2.2
  circle C3 centre (-22.8469, 24.5003) radius 2.2
  circle C4 centre (-22.8469, -24.5003) radius 2.2
  closed curve K12 centre (0, 0)
  dimension "d698" Text1-Height = 8
extrude "Extrude43" add sketch "Sketch23" along normal blind 0.5
work_plane "WorkPlane2" AlongDistance 58
sketch "Shell" plane through (0, 0, 58) normal (0, 0, 1) x axis (1, 0, 0)
  curve K1 (0, -55) -> (0, 55)
  curve K2 (45, 0) -> (-45, 0)
  curve K3 (0, -53) -> (0, 53)
  curve K4 (43, 0) -> (-43, 0)
  line L1 (-8.2, -51) -> (8.2, -51)
  line L2 (-8.2, -55) -> (-8.2, -51)
  line L3 (8.2, -55) -> (-8.2, -55)
  line L4 (8.2, -51) -> (8.2, -55)
  line L5 (-8.2, -55) -> (8.2, -51)
  line L6 (8.2, -55) -> (-8.2, -51)
  curve K5 (0, -50.6) -> (0, 50.6)
  curve K6 (40.6, 0) -> (-40.6, 0)
  line L7 (-18.3979, -47.9039) -> (-8.2, -52.0274)
  line L8 (-17.371, -45.7346) -> (-18.3979, -47.9039)
  line L9 (18.3979, -47.9039) -> (8.2, -52.0274)
  line L10 (17.371, -45.7346) -> (18.3979, -47.9039)
  curve K7 (0, -48.6) -> (0, 48.6)
  curve K8 (38.6, 0) -> (-38.6, 0)
  line L11 (-16.5153, -43.9269) -> (-17.371, -45.7346)
  line L12 (-19.2536, -49.7115) -> (-18.3979, -47.9039)
  line L13 (19.2536, -49.7115) -> (18.3979, -47.9039)
  line L14 (16.5153, -43.9269) -> (17.371, -45.7346)
  line L15 (-22.8469, -20.228) -> (-19.1469, -22.3642)
  line L16 (-26.5469, -22.3642) -> (-22.8469, -20.228)
  line L17 (-26.5469, -26.6365) -> (-26.5469, -22.3642)
  line L18 (-22.8469, -28.7727) -> (-26.5469, -26.6365)
  line L19 (-19.1469, -26.6365) -> (-22.8469, -28.7727)
  line L20 (-19.1469, -22.3642) -> (-19.1469, -26.6365)
  line L21 (22.8469, -20.228) -> (26.5469, -22.3642)
  line L22 (19.1469, -22.3642) -> (22.8469, -20.228)
  line L23 (19.1469, -26.6365) -> (19.1469, -22.3642)
  line L24 (22.8469, -28.7727) -> (19.1469, -26.6365)
  line L25 (26.5469, -26.6365) -> (22.8469, -28.7727)
  line L26 (26.5469, -22.3642) -> (26.5469, -26.6365)
  line L27 (-22.8469, 28.7727) -> (-19.1469, 26.6365)
  line L28 (-26.5469, 26.6365) -> (-22.8469, 28.7727)
  line L29 (-26.5469, 22.3642) -> (-26.5469, 26.6365)
  line L30 (-22.8469, 20.228) -> (-26.5469, 22.3642)
  line L31 (-19.1469, 22.3642) -> (-22.8469, 20.228)
  line L32 (-19.1469, 26.6365) -> (-19.1469, 22.3642)
  line L33 (22.8469, 28.7727) -> (26.5469, 26.6365)
  line L34 (19.1469, 26.6365) -> (22.8469, 28.7727)
  line L35 (19.1469, 22.3642) -> (19.1469, 26.6365)
  line L36 (22.8469, 20.228) -> (19.1469, 22.3642)
  line L37 (26.5469, 22.3642) -> (22.8469, 20.228)
  line L38 (26.5469, 26.6365) -> (26.5469, 22.3642)
  line L39 (-8.2, -47.4907) -> (-8.2, -51)
  line L40 (8.2, -47.4907) -> (8.2, -51)
  closed curve K9 centre (0, 0)
  closed curve K10 centre (0, 0)
  closed curve K11 centre (0, 0)
  closed curve K12 centre (0, 0)
  circle C1 centre (22.8469, 24.5003) radius 2.2
  circle C2 centre (-22.8469, 24.5003) radius 2.2
  circle C3 centre (-22.8469, -24.5003) radius 2.2
  circle C4 centre (22.8469, -24.5003) radius 2.2
  circle C5 centre (22.8469, 24.5003) radius 6
  circle C6 centre (-22.8469, 24.5003) radius 6
  circle C7 centre (-22.8469, -24.5003) radius 6
  circle C8 centre (22.8469, -24.5003) radius 6
  point P3 (0, 55)
  point P4 (0, -55)
  point P5 (-45, 0)
  point P6 (45, 0)
  point P1 (0, 0)
  point P2 (0, 0)
  point P8 (0, 53)
  point P9 (0, -53)
  point P10 (-43, 0)
  point P11 (43, 0)
  point P16 (0, -53)
  point P18 (0, 50.6)
  point P19 (0, -50.6)
  point P20 (-40.6, 0)
  point P21 (40.6, 0)
  point P17 (0, 0)
  point P22 (-8.2, -52.0274)
  point P23 (-18.3979, -47.9039)
  point P24 (-17.371, -45.7346)
  point P25 (8.2, -52.0274)
  point P26 (18.3979, -47.9039)
  point P27 (17.371, -45.7346)
  point P29 (0, 48.6)
  point P30 (0, -48.6)
  point P31 (-38.6, 0)
  point P32 (38.6, 0)
  point P33 (-16.5153, -43.9269)
  point P34 (-19.2536, -49.7115)
  point P35 (19.2536, -49.7115)
  point P36 (16.5153, -43.9269)
  point P39 (-22.8469, -24.5003)
  point P47 (-22.8469, -24.5003)
  point P37 (22.8469, -24.5003)
  point P54 (22.8469, -24.5003)
  point P38 (-22.8469, 24.5003)
  point P61 (-22.8469, 24.5003)
  point P40 (22.8469, 24.5003)
  point P68 (22.8469, 24.5003)
  point P69 (22.8469, 24.5003)
  point P70 (-22.8469, 24.5003)
  point P73 (-8.2, -47.4907)
  point P14 (-8.2, -55)
  point P15 (8.2, -55)
  point P13 (-8.2, -51)
  coincident K9 P3
  coincident K9 P4
  coincident K9 P5
  coincident K9 P6
  coincident P1 P2
  vertical K1
  coincident K10 P8
  coincident K10 P9
  coincident K10 P10
  coincident K10 P11
  concentric K9 K10
  perpendicular K2 K3
  horizontal L1
  perpendicular L1 L2
  parallel L1 L3
  parallel L2 L4
  coincident L5 P16
  coincident L6 P16
  coincident P9 P16
  coincident K11 P18
  coincident K11 P19
  coincident K11 P20
  coincident K11 P21
  coincident P1 P17
  perpendicular K2 K5
  coincident K10 P22
  coincident L2 P22
  coincident K10 P23
  coincident K11 P24
  coincident L4 P25
  coincident K10 P25
  coincident K10 P26
  coincident K11 P27
  coincident K12 P29
  coincident K12 P30
  coincident K12 P31
  coincident K12 P32
  concentric K11 K12
  parallel K1 K7
  coincident K12 P33
  parallel L8 L11
  coincident K9 P34
  parallel L8 L12
  parallel L10 L13
  coincident K9 P35
  coincident K12 P36
  parallel L10 L14
  coincident P39 P47
  coincident P37 P54
  coincident P38 P61
  coincident P40 P68
  coincident P68 P69
  coincident P61 P70
  concentric C3 C7
  concentric C4 C8
  coincident K12 P73
  perpendicular L1 L39
  perpendicular L1 L40
  dimension "d132" distance K9 = 110
  dimension "d133" = 90
  dimension "d134" distance K10 = 106
  dimension "d135" = 86
  dimension "d136" distance P14 P15 = 16.4
  dimension "d137" distance P13 P14 = 4
  dimension "d138" distance K11 = 101.2
  dimension "d139" = 81.2
  dimension "d140" distance P22 P23 = 11
  dimension "d141" distance P23 P24 = 2.4
  dimension "d142" distance P25 P26 = 11
  dimension "d143" distance P26 P27 = 2.4
  dimension "d144" distance K12 = 97.2
  dimension "d145" = 77.2
  dimension "d147" distance P47 L20 = 3.7
  dimension "d148" distance P54 L26 = 3.7
  dimension "d149" distance P61 L32 = 3.7
  dimension "d150" distance P68 L38 = 3.7
  dimension "d151" diameter C5 = 12
  dimension "d152" diameter C6 = 12
  dimension "d153" diameter C7 = 12
  dimension "d154" diameter C8 = 12
extrude "Extrude16" new body sketch "Shell" profile of K9 K10 L2 L4 K11 L8 L10 K12 L11 L12 L13 L14 L39 L40 against normal blind 16 bodies "Closed Shell"
extrude "Extrude17" add sketch "Shell" profile of K9 K10 L2 L4 K11 K12 L39 L40 against normal blind 5.8
copy_paste_bodies "CopyPasteBodies1"
move "Move1"
combine "Combine1" bodies "Driver Clamp (1)"
offset_faces "OffsetFaces1" distance -0.2
extrude "Extrude19" add sketch "Shell" profile of K10 K11 L8 L10 K12 L11 L14 C5 C6 C7 C8 L39 L40 against normal blind 4
extrude "Extrude20" add sketch "Shell" profile of C1 C2 C3 C4 L15 L16 L17 L18 L19 L20 L21 L22 L23 L24 L25 L26 L27 L28 L29 L30 L31 L32 L33 L34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 against normal blind 16
extrude "Extrude21" cut sketch "Shell" profile of C1 C2 C3 C4 L15 L16 L17 L18 L19 L20 L21 L22 L23 L24 L25 L26 L27 L28 L29 L30 L31 L32 L33 L34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 against normal blind 11.5
chamfer "Chamfer5" distance 1.8 distance 4
chamfer "Chamfer6" distance 2 distance 1.8
chamfer "Chamfer7" distance 4
sketch "Sketch16" plane through (0, 0, 42) normal (0, 0, -1) x axis (1, 0, 0)
  line L1 (-18.4338, 47.8837) -> (-18.4335, 47.8831)
  curve K1 (-18.4338, 47.8837) -> (-8.2, 52.0276)
  line L2 (-8.2, 54.0792) -> (-8.2, 52.0276)
  line L3 (8.2, 52.0276) -> (8.2, 54.0792)
  curve K2 (8.2, 52.0276) -> (18.4338, 47.8837)
  line L4 (18.4335, 47.8831) -> (18.4338, 47.8837)
  line L5 (-45, -5.7) -> (45, -5.7)
  line L6 (-45, 5.7) -> (-45, -5.7)
  line L7 (45, 5.7) -> (-45, 5.7)
  line L8 (45, -5.7) -> (45, 5.7)
  line L9 (-45, 5.7) -> (45, -5.7)
  line L10 (45, 5.7) -> (-45, -5.7)
  closed curve K3 centre (0, 0)
  closed curve K4 centre (0, 0)
  point P15 (0, 0)
  point P1 (0, 0)
  point P13 (-45, 5.7)
  point P14 (45, 5.7)
  point P12 (-45, -5.7)
  horizontal L5
  perpendicular L5 L6
  parallel L5 L7
  parallel L6 L8
  coincident L9 P15
  coincident L10 P15
  coincident P1 P15
  dimension "d547" distance P13 P14 = 90
  dimension "d548" distance P12 P13 = 11.4
extrude "Extrude30" cut sketch "Sketch16" profile of K3 K4 L5 L7 against normal blind 9.1
chamfer "Chamfer9" distance 1.73 Rotate Angle 50
copy_paste_bodies "CopyPasteBodies2"
move "Move2"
